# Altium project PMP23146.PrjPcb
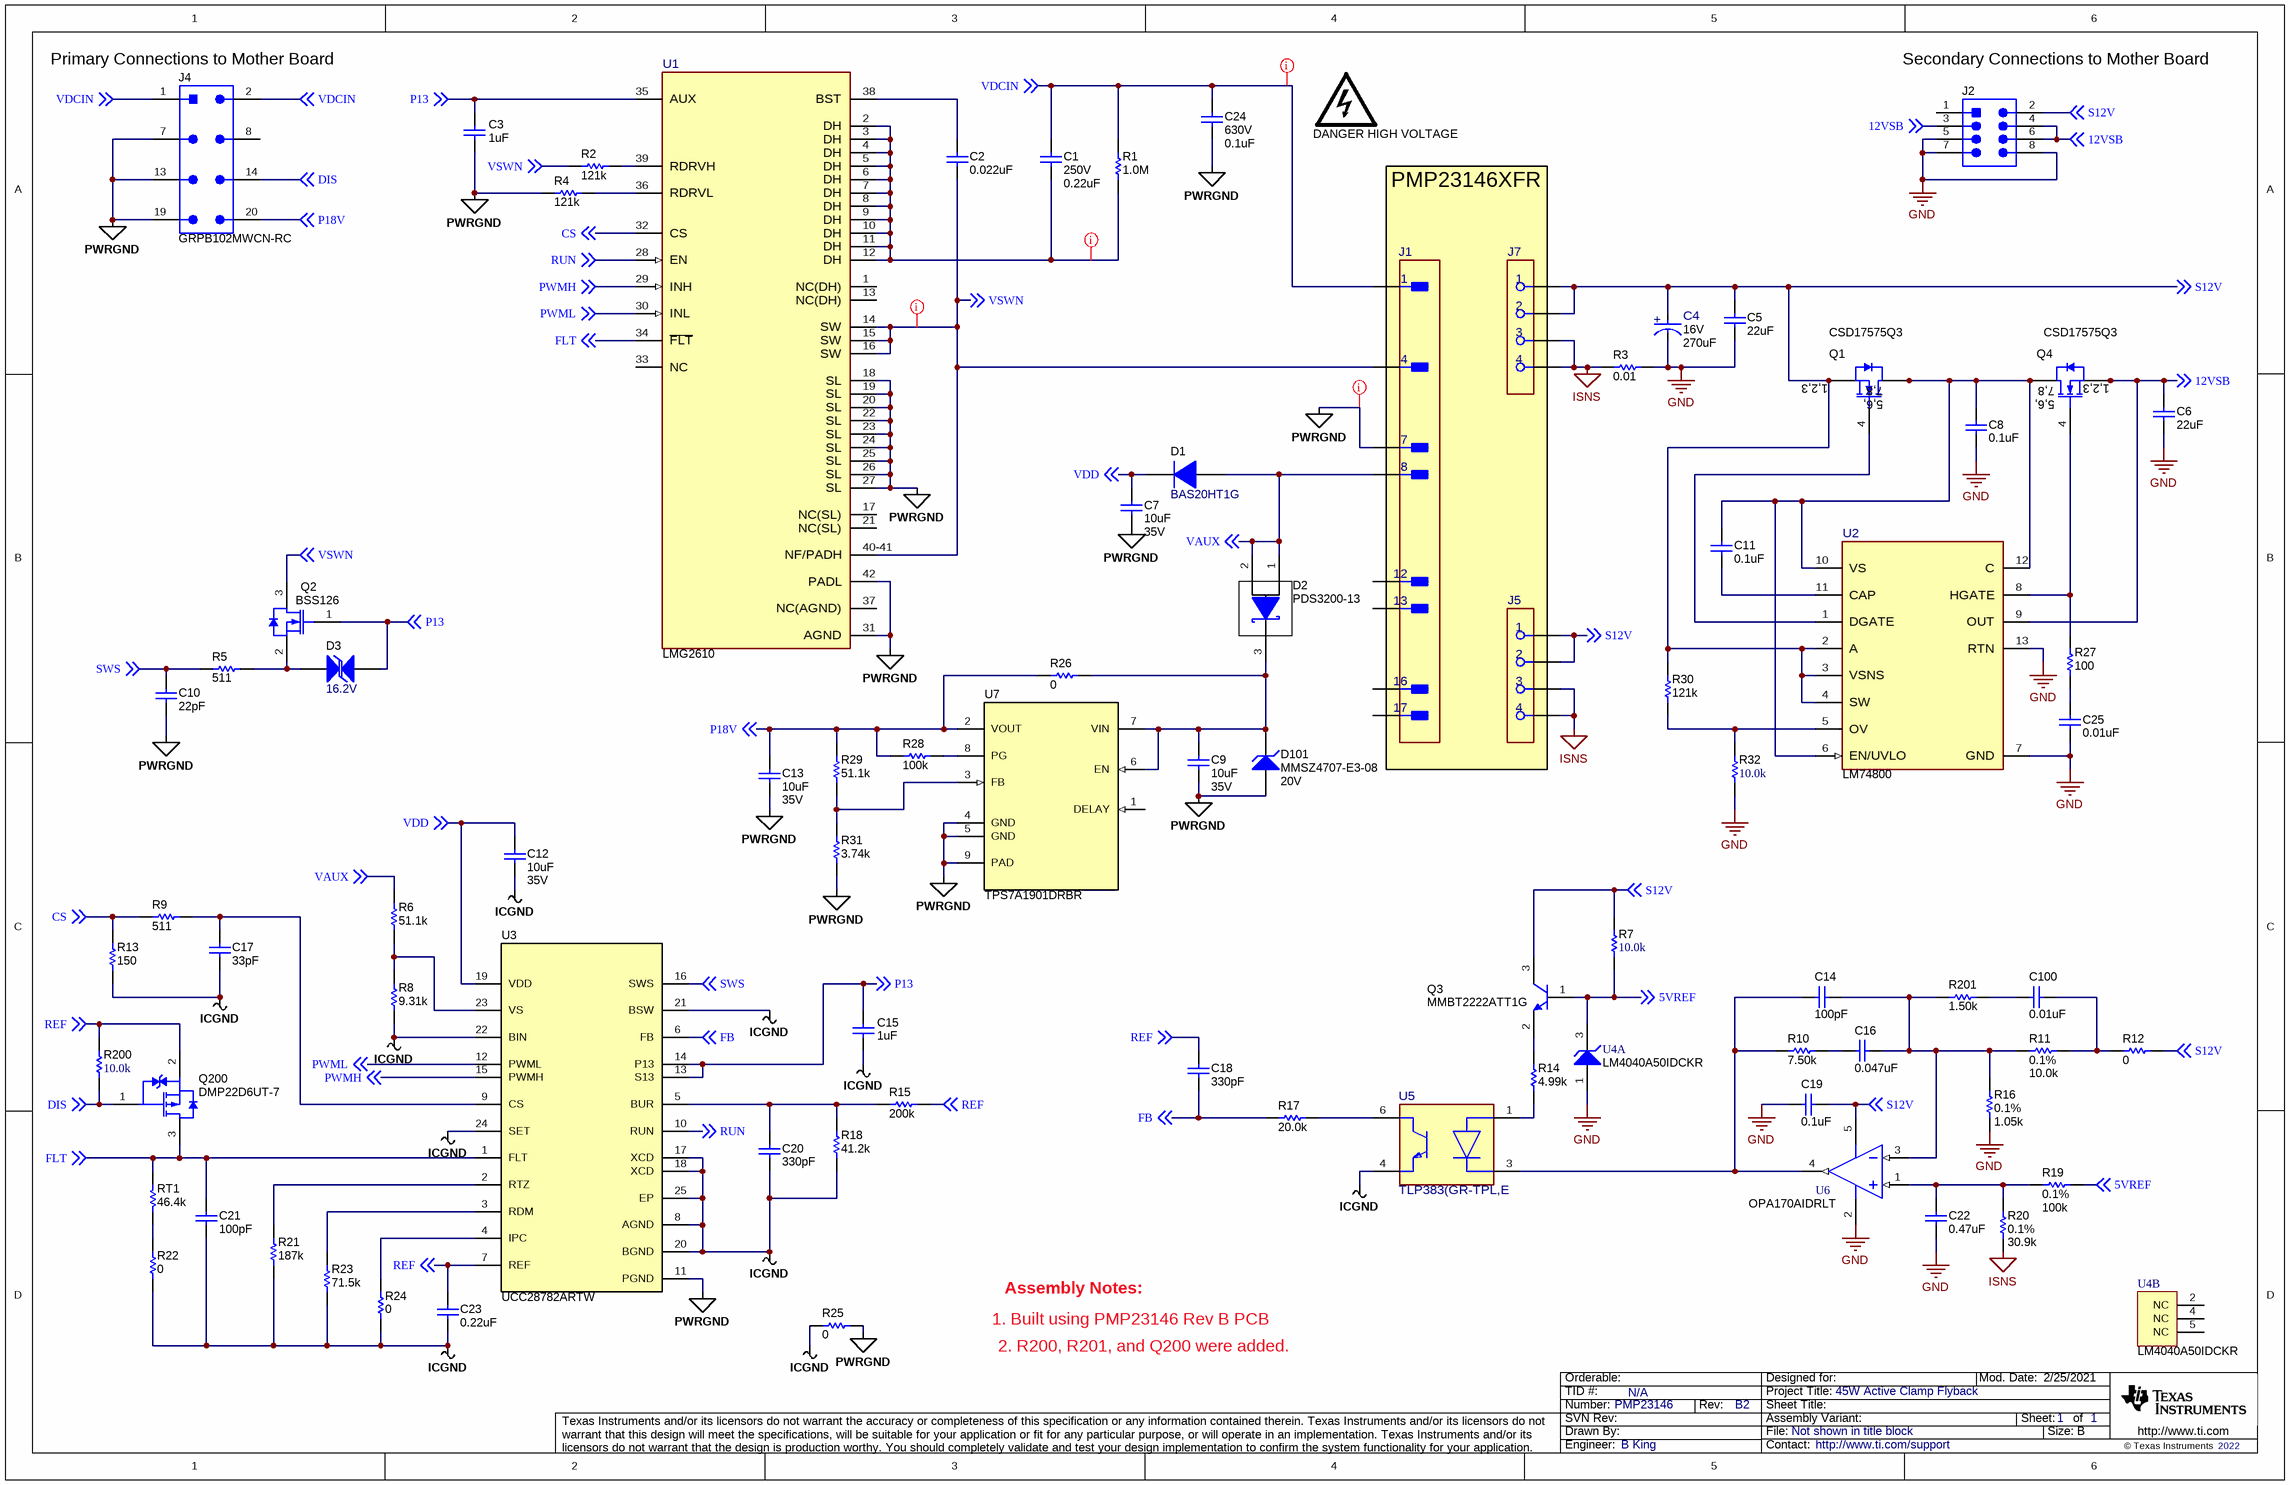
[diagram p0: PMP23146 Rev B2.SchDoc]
CopyrightYear: 2022; PCB_Layout: B King; PCB_Rev: B2; PRJ_Engineer: B King; PRJ_Number: PMP23146; PRJ_Title: 45W Active Clamp Flyback; SCH_Rev: B2; TechSupport: http://www.ti.com/support; TID: N/A
1 sheet, 83 parts. Net scope: global (net labels, ports and power ports of the same name join across sheets).
Board file: PMP23146 Rev B2.PcbDoc

## Sheet PMP23146 Rev B2.SchDoc
size 431 x 279 mm; Date: Not shown in title block; ApprovedBy: Not shown in title block; CheckedBy: Not shown in title block; Author: Not shown in title block; CompanyName: Not shown in title block; Engineer: Not shown in title block; Organization: Not shown in title block; Address1: Not shown in title block; Address2: Not shown in title block; Address3: Not shown in title block; Address4: Not shown in title block; DocumentNumber: 1; Revision: Use project parameter SCH_Rev; SheetNumber: 1; SheetTotal: 1; PageSetup: Record=PageOptions¦CenterHorizontal=True¦CenterVertical=True¦PrintScale=1.00¦XCorrection=1.00¦YCorrection=1.00¦PrintKind=0¦BorderSize=5000000¦LeftOffset=0¦BottomOffset=0¦Orientation=2¦PaperLength=1000¦PaperWidth=1000¦Scale=100¦PaperSource=15¦PrintQuality=600¦MediaType=1¦DitherType=10¦PaperKind=Letter¦PrintScaleMode=1

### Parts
C1  VDC_V: 250V  ValueDisplayed: 0.22uF  [1206_190L]  (hidden comment: C3216X7T2E224K160AA)
C2  ValueDisplayed: 0.022uF  [0402S]  (hidden comment: GRM155R71H223KA12D)
C3  ValueDisplayed: 1uF  [0603S]  (hidden comment: C1608X7R1E105K080AB)
C4  VDC_V: 16V  ValueDisplayed: 270uF  [FP-APSG160ELL271MF08J_RADIAL-MFG]  (hidden comment: APSG160ELL271MF08J)
C5  ValueDisplayed: 22uF  [1206_180L]  (hidden comment: C3216X5R1V226M160AC)
C6  ValueDisplayed: 22uF  [1206_180L]  (hidden comment: C3216X5R1V226M160AC)
C7  ValueDisplayed: 10uF  VDC_V: 35V  [0603S]  (hidden comment: GRM188R6YA106MA73D)
C8  ValueDisplayed: 0.1uF  [0402S]  (hidden comment: GRM155R71E104KE14D)
C9  ValueDisplayed: 10uF  VDC_V: 35V  [0603S]  (hidden comment: GRM188R6YA106MA73D)
C10  ValueDisplayed: 22pF  [0402S]  (hidden comment: GRM1555C1H220JA01D)
C11  ValueDisplayed: 0.1uF  [0402S]  (hidden comment: GRM155R71E104KE14D)
C12  ValueDisplayed: 10uF  VDC_V: 35V  [0603S]  (hidden comment: GRM188R6YA106MA73D)
C13  ValueDisplayed: 10uF  VDC_V: 35V  [0603S]  (hidden comment: GRM188R6YA106MA73D)
C14  ValueDisplayed: 100pF  [0402S]  (hidden comment: GRM1555C1H101JA01D)
C15  ValueDisplayed: 1uF  [0603S]  (hidden comment: C1608X7R1E105K080AB)
C16  ValueDisplayed: 0.047uF  [0402S]  (hidden comment: GRM155R71E473KA88D)
C17  ValueDisplayed: 33pF  [0402S]  (hidden comment: GRM1555C1H330JA01D)
C18  ValueDisplayed: 330pF  [0402S]  (hidden comment: GRM155R71H331KA01D)
C19  ValueDisplayed: 0.1uF  [0402S]  (hidden comment: GRM155R71E104KE14D)
C20  ValueDisplayed: 330pF  [0402S]  (hidden comment: GRM155R71H331KA01D)
C21  ValueDisplayed: 100pF  [0402S]  (hidden comment: GRM1555C1H101JA01D)
C22  ValueDisplayed: 0.47uF  [0402S]  (hidden comment: C1005X5R1A474K050BB)
C23  ValueDisplayed: 0.22uF  [0402S]  (hidden comment: GRM155R71C224KA12D)
C24  VDC_V: 630V  ValueDisplayed: 0.1uF  [1808_215_L]  (hidden comment: C1808W104KBRACTU)
C25  ValueDisplayed: 0.01uF  [0402S]  (hidden comment: GCM155R71E103KA37D)
C100  ValueDisplayed: 0.01uF  [0402S]  (hidden comment: GCM155R71E103KA37D)
D1  BAS20HT1G  [SOD-323]
D2  PDS3200-13  [POWERDI5]
D3  value 16.2V  [SOD-323-Bi]  (hidden comment: DF2B18FU)
D101  MMSZ4707-E3-08  value 20V  [SOD-123]
J1  LPPB171NFFN-RC  [FP-GRPB171VWVN-RC_HDR17-MFG]  (value not drawn)
J2  GRPB042MWCN-RC  [Sullins_GRPB042MWCN]  (value not drawn)
J4  GRPB102MWCN-RC  [Sullins_GRPB102MWCN-modified]
J5  LPPB041NFFN-RC  [FP-LPPB041NFFN-RC_HDR04-MFG]  (value not drawn)
J7  LPPB041NFFN-RC  [FP-LPPB041NFFN-RC_HDR04-MFG]  (value not drawn)
LOGO1  DANGER HIGH VOLTAGE  [IEC_HighVoltage_Small]  (no BOM)
Q1  CSD17575Q3  [DQG0008A_NV]
Q2  BSS126  [SOT-23L]
Q3  MMBT2222ATT1G  [SOT-416]
Q4  CSD17575Q3  [DQG0008A_NV]
Q200  DMP22D6UT-7  [SOT-523]
R1  ValueDisplayed: 1.0M  [1206L]  (hidden comment: CRCW12061M00JNEA)
R2  ValueDisplayed: 121k  [0402S]  (hidden comment: CRCW0402121KFKED)
R3  ValueDisplayed: 0.01  [1206L]  (hidden comment: CSR1206FK10L0)
R4  ValueDisplayed: 121k  [0402S]  (hidden comment: CRCW0402121KFKED)
R5  ValueDisplayed: 511  [0402S]  (hidden comment: CRCW0402511RFKED)
R6  ValueDisplayed: 51.1k  [0402S]  (hidden comment: CRCW040251K1FKED)
R7  ValueDisplayed: 10.0k  [0402S]  (hidden comment: CRCW040210K0FKED)
R8  ValueDisplayed: 9.31k  [0402S]  (hidden comment: CRCW04029K31FKED)
R9  ValueDisplayed: 511  [0402S]  (hidden comment: CRCW0402511RFKED)
R10  ValueDisplayed: 7.50k  [0402S]  (hidden comment: CRCW04027K50FKED)
R11  Tolerance_%: 0.1%  ValueDisplayed: 10.0k  [0402S]  (hidden comment: MCR01MRTF1002)
R12  ValueDisplayed: 0  [0402S]  (hidden comment: CRCW04020000Z0ED)
R13  ValueDisplayed: 150  [0402S]  (hidden comment: CRCW0402150RFKED)
R14  ValueDisplayed: 4.99k  [0402S]  (hidden comment: CRCW04024K99FKED)
R15  ValueDisplayed: 200k  [0402S]  (hidden comment: CRCW0402200KFKED)
R16  Value1: 0.1%  ValueDisplayed: 1.05k  [0402S]  (hidden comment: ERA-2AEB1051X)
R17  ValueDisplayed: 20.0k  [0402S]  (hidden comment: CRCW040220K0FKED)
R18  ValueDisplayed: 41.2k  [0402S]  (hidden comment: CRCW040241K2FKED)
R19  Value1: 0.1%  ValueDisplayed: 100k  [0402S]  (hidden comment: RG1005P-104-B-T5)
R20  Value1: 0.1%  ValueDisplayed: 30.9k  [0402S]  (hidden comment: ERA-2AEB3092X)
R21  ValueDisplayed: 187k  [0402S]  (hidden comment: CRCW0402187KFKED)
R22  ValueDisplayed: 0  [0402S]  (hidden comment: CRCW04020000Z0ED)
R23  ValueDisplayed: 71.5k  [0402S]  (hidden comment: CRCW040271K5FKED)
R24  ValueDisplayed: 0  [0402S]  (hidden comment: CRCW04020000Z0ED)
R25  ValueDisplayed: 0  [0402S]  (hidden comment: CRCW04020000Z0ED)
R26  ValueDisplayed: 0  [0402S]  (hidden comment: CRCW04020000Z0ED)
R27  ValueDisplayed: 100  [0402S]  (hidden comment: CRCW0402100RFKED)
R28  ValueDisplayed: 100k  [0402S]  (hidden comment: CRCW0402100KFKED)
R29  ValueDisplayed: 51.1k  [0402S]  (hidden comment: CRCW040251K1FKED)
R30  ValueDisplayed: 121k  [0402S]  (hidden comment: CRCW0402121KFKED)
R31  ValueDisplayed: 3.74k  [0402S]  (hidden comment: CRCW04023K74FKED)
R32  ValueDisplayed: 10.0k  [0402S]  (hidden comment: CRCW040210K0FKED)
R200  ValueDisplayed: 10.0k  [0402S]  (hidden comment: CRCW040210K0FKED)
R201  ValueDisplayed: 1.50k  [0402S]  (hidden comment: CRCW04021K50FKED)
RT1  ValueDisplayed: 46.4k  [0603L]  (hidden comment: CRCW060346K4FKEA)
U1  LMG2610  [RRG0040A-C01-MFG]
U2  LM74800  [DRR0012E-MFG]
U3  UCC28782ARTW  [RTW0024B]
U4  LM4040A50IDCKR  [DCK0005A_N]  (parts A,B of 2)
U5  TLP383(GR-TPL,E  [FP-TLP383(GR-TPL,E_SO6-4-MFG]
U6  OPA170AIDRLT  [DRL0005A]
U7  TPS7A1901DRBR  [DRB0008B]

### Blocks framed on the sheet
PMP23146XFR: J1 J5 J7

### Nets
GND: C4.1(CATHODE) C5.1 C6.2 C8.2 C19.1 C22.1 C25.1 J2.5 J2.7 J2.8 R3.2 R16.1 R32.1 U2.7(GND) U2.13(RTN) U4.1(ANODE) U6.2(V-)
ICGND: C12.2 C15.1 C17.2 C20.1 C21.2 C23.2 R8.1 R13.1 R18.1 R21.1 R22.1 R23.1 R24.1 R25.2 U3.8(AGND) U3.17(XCD) U3.18(XCD) U3.20(BGND) U3.21(BSW) U3.22(BIN) U3.24(SET) U3.25(EP) U5.4(Emitter)
ISNS: J5.3 J5.4 J7.3 J7.4 R3.1 R20.1
PWRGND: C3.1 C7.2 C9.2 C10.1 C13.2 C24.2 D101.2(A) J1.7 J4.7 J4.13 J4.19 R4.2 R25.1 R31.1 U1.18(SL) U1.19(SL) U1.20(SL) U1.22(SL) U1.23(SL) U1.24(SL) U1.25(SL) U1.26(SL) U1.27(SL) U1.31(AGND) U1.42(PADL) U3.11(PGND) U7.4(GND) U7.5(GND) U7.9(PAD)
5VREF: Q3.1(B) R7.1 R19.1 U4.3(CATHODE) ; off-sheet 5VREF
12VSB: C6.1 J2.3 J2.4 J2.6 Q4.1(S) Q4.2(S) Q4.3(S) U2.9(OUT) ; off-sheet 12VSB
CS: R9.1 R13.2 U1.32(CS) ; off-sheet CS
DIS: J4.14 Q200.1(G) R200.1 ; off-sheet DIS
FB: C18.1 R17.1 U3.6(FB) ; off-sheet FB
FLT: C21.1 Q200.3(D) RT1.1 U1.34(~{FLT}) U3.1(FLT) ; off-sheet FLT
P13: C3.2 C15.2 D3.2 Q2.1(G) U1.35(AUX) U3.13(S13) U3.14(P13) ; off-sheet P13
P18V: C13.1 J4.20 R26.2 R28.2 R29.2 U7.2(VOUT) ; off-sheet P18V
PWMH: U1.29(INH) U3.15(PWMH) ; off-sheet PWMH
PWML: U1.30(INL) U3.12(PWML) ; off-sheet PWML
REF: C18.2 C23.1 Q200.2(S) R15.2 R200.2 U3.7(REF) ; off-sheet REF
RUN: U1.28(EN) U3.10(RUN) ; off-sheet RUN
S12V: C4.2(ANODE) C5.2 C19.2 J2.2 J5.1 J5.2 J7.1 J7.2 Q1.1(S) Q1.2(S) Q1.3(S) Q3.3(C) R7.2 R12.1 R30.2 U2.2(A) U2.3(VSNS) U2.4(SW) U6.5(V+) ; off-sheet S12V
SWS: C10.2 R5.1 U3.16(SWS) ; off-sheet SWS
VAUX: D1.2(A) D2.1(A) D2.2(A) J1.8 R6.2 ; off-sheet VAUX
VDCIN: C1.1 C24.1 J1.1 J4.1 J4.2 R1.2 ; off-sheet VDCIN
VDD: C7.1 C12.1 D1.1(K) U3.19(VDD) ; off-sheet VDD
VSWN: C2.2 J1.4 Q2.3(D) R2.1 U1.14(SW) U1.15(SW) U1.16(SW) U1.40-41(NF/PADH) ; off-sheet VSWN
NetC1_2: C1.2 R1.1 U1.2(DH) U1.3(DH) U1.4(DH) U1.5(DH) U1.6(DH) U1.7(DH) U1.8(DH) U1.9(DH) U1.10(DH) U1.11(DH) U1.12(DH)
NetC2_1: C2.1 U1.38(BST)
NetC8_1: C8.1 C11.1 Q1.5(D) Q1.6(D) Q1.7(D) Q1.8(D) Q1.9(D) Q4.5(D) Q4.6(D) Q4.7(D) Q4.8(D) Q4.9(D) U2.6(EN/UVLO) U2.10(VS) U2.12(C)
NetC9_1: C9.1 D2.3(K) D101.1(K) R26.1 U7.6(EN) U7.7(VIN)
NetC11_2: C11.2 U2.11(CAP)
NetC14_1: C14.1 R10.1 U5.3(Cathode) U6.4(OUT)
NetC14_2: C14.2 C16.1 R11.1 R16.2 R201.1 U6.3(IN-)
NetC16_2: C16.2 R10.2
NetC17_1: C17.1 R9.2 U3.9(CS)
NetC20_2: C20.2 R15.1 R18.2 U3.5(BUR)
NetC22_2: C22.2 R19.2 R20.2 U6.1(IN+)
NetC25_2: C25.2 R27.1
NetC100_1: C100.1 R201.2
NetC100_2: C100.2 R11.2 R12.2
NetD3_1: D3.1 Q2.2(S) R5.2
NetQ1_4: Q1.4(G) U2.1(DGATE)
NetQ3_2: Q3.2(E) R14.2
NetQ4_4: Q4.4(G) R27.2 U2.8(HGATE)
NetR2_2: R2.2 U1.39(RDRVH)
NetR4_1: R4.1 U1.36(RDRVL)
NetR6_1: R6.1 R8.2 U3.23(VS)
NetR14_1: R14.1 U5.1(Anode)
NetR17_2: R17.2 U5.6(Collector)
NetR21_2: R21.2 U3.2(RTZ)
NetR22_2: R22.2 RT1.2
NetR23_2: R23.2 U3.3(RDM)
NetR24_2: R24.2 U3.4(IPC)
NetR28_1: R28.1 U7.8(PG)
NetR29_1: R29.1 R31.2 U7.3(FB)
NetR30_1: R30.1 R32.2 U2.5(OV)

Not connected (* = marked no-connect by the designer): J1 12 13 16 17; J2 1; J4 8; U1 1(NC(DH)) 13(NC(DH)) 17(NC(SL)) 21(NC(SL)) 33(NC) 37(NC(AGND)); U4 2(NC) 4(NC) 5(NC); U7 1(DELAY)

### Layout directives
net class 400V: NetC1_2, VDCIN, VSWN
net class Primary LV: PWRGND

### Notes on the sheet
- (near J4) Primary Connections to Mother Board
- (near J2) Secondary Connections to Mother Board
- Assembly Notes:
- 2. R200, R201, and Q200 were added.
- 1. Built using PMP23146 Rev B PCB

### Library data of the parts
C1 = CMP-0008726-2: CAP, CERM, 0.22 uF, 250 V, +/- 10%, X7T, 1206_190; Manufacturer: TDK; TaMin_C: -55°C; Polarized: N; SizeAreaWB_mm2: 10.92; Value1: Unknown; U/M: EA; Value: 0.22uF; TaMax_C: 125°C; SizeZ_mm: 1.9; SizeX_mm: 3.2; SizeY_mm: 1.6; Cap_Case: 1206; SizeArea_mm2: 5.12; Cap_F: 220nF; AEC Category: Q200
C2 = CMP-0006684-2: CAP, CERM, 0.022 uF, 50 V, +/- 10%, X7R, 0402; Manufacturer: MuRata; TaMin_C: -55°C; Polarized: N; SizeAreaWB_mm2: 3; Value1: Unknown; U/M: EA; TaMax_C: 125°C; SizeZ_mm: 0.6; SizeX_mm: 1; SizeY_mm: 0.5; Cap_Case: 0402; Value2: 50V; Cap_F: 22nF; AEC Category: Q200
C3 C15 = CMP-0007040-4: CAP, CERM, 1 µF, 25 V, +/- 10%, X7R, 0603; Manufacturer: TDK; Polarized: N; CompType: Capacitor; Value: 1uF; U/M: EA; Cap_F: 1µF; Value1: Unknown; VDC_V: 25V; TaMin_C: -55°C; TaMax_C: 125°C; Cap_Case: 0603; AEC Category: Q200; SizeArea_mm2: 1.28; SizeAreaWB_mm2: 4.68; SizeX_mm: 1.6; SizeY_mm: 0.8; SizeZ_mm: 1
C4 = CMP-0091874-1: 270µF 16V Aluminum - Polymer Capacitors Radial, Can 10mOhm 20000 Hrs @ 105°C; Manufacturer: Nippon Chemi-Con; IRMS_A: 5.08A; AEC Qualified: No; Esr: 0.01; Tolerance_%: 20%; SizeZ_mm: 9.2mm; Dissipation Factor: 12%; Life: 20000Hours; Leakage Current: 864uA
C5 C6 = CMP-0008667-2: CAP, CERM, 22 uF, 35 V, +/- 20%, X5R, 1206; Manufacturer: TDK; TaMin_C: -55°C; ESR_ohm: 2.398m; Polarized: N; SizeAreaWB_mm2: 10.92; Value1: 0.002398 ohm; U/M: EA; Value: 22uF; TaMax_C: 85°C; SizeZ_mm: 1.8; SizeX_mm: 3.2; SizeY_mm: 1.6; Cap_Case: 1206_180; Value2: 35V; SizeArea_mm2: 5.12; Cap_F: 22µF; IRMS_A: 4.68507A; AEC Category: Q200
C7 C9 C12 C13 = CMP-0007355-6: CAP, CERM, 10 uF, 35 V, +/- 20%, X5R, 0603; Manufacturer: Murata; TaMax_C: 85°C; Value1: Unknown; TaMin_C: -55°C; Value: 10uF; SizeZ_mm: 1; SizeArea_mm2: 1.28; AEC Category: Q200; Cap_F: 10µF; SizeY_mm: 0.8; AEC Qualified: N; SizeX_mm: 1.6; SizeAreaWB_mm2: 4.68; U/M: EA; Cap_Case: 0603
C8 C11 C19 = CMP-0006659-2: CAP, CERM, 0.1 uF, 25 V, +/- 10%, X7R, 0402; Manufacturer: MuRata; TaMin_C: -55°C; Polarized: N; SizeAreaWB_mm2: 3; Value1: Unknown; U/M: EA; Value: 0.1uF; TaMax_C: 125°C; SizeZ_mm: 0.6; SizeX_mm: 1; SizeY_mm: 0.5; Cap_Case: 0402; Value2: 25V; Cap_F: 100nF; AEC Category: Q200
C10 = CMP-0006439-2: CAP, CERM, 22 pF, 50 V, +/- 5%, C0G/NP0, 0402; Manufacturer: MuRata; TaMin_C: -55°C; Polarized: N; SizeAreaWB_mm2: 3; Value1: Unknown; U/M: EA; Value: 22pF; TaMax_C: 125°C; SizeZ_mm: 0.6; SizeX_mm: 1; SizeY_mm: 0.5; Cap_Case: 0402; Value2: 50V; AEC Category: Q200
C14 C21 = CMP-0006410-2: CAP, CERM, 100 pF, 50 V, +/- 5%, C0G/NP0, 0402; Manufacturer: MuRata; TaMin_C: -55°C; Polarized: N; SizeAreaWB_mm2: 3; Value1: Unknown; U/M: EA; Value: 100pF; TaMax_C: 125°C; SizeZ_mm: 0.6; SizeX_mm: 1; SizeY_mm: 0.5; Cap_Case: 0402; Value2: 50V; AEC Category: Q200
C16 = CMP-0006669-2: CAP, CERM, 0.047 uF, 25 V, +/- 10%, X7R, 0402; Manufacturer: MuRata; TaMin_C: -55°C; Polarized: N; SizeAreaWB_mm2: 3; Value1: Unknown; U/M: EA; TaMax_C: 125°C; SizeZ_mm: 0.6; SizeX_mm: 1; SizeY_mm: 0.5; Cap_Case: 0402; Value2: 25V; Cap_F: 47nF; AEC Category: Q200
C17 = CMP-0006454-2: CAP, CERM, 33 pF, 50 V, +/- 5%, C0G/NP0, 0402; Manufacturer: MuRata; TaMin_C: -55°C; Polarized: N; SizeAreaWB_mm2: 3; Value1: Unknown; U/M: EA; Value: 33pF; TaMax_C: 125°C; SizeZ_mm: 0.6; SizeX_mm: 1; SizeY_mm: 0.5; Cap_Case: 0402; Value2: 50V; AEC Category: Q200
C18 C20 = CMP-0006687-2: CAP, CERM, 330 pF, 50 V, +/- 10%, X7R, 0402; Manufacturer: MuRata; TaMin_C: -55°C; Polarized: N; SizeAreaWB_mm2: 3; Value1: Unknown; U/M: EA; Value: 330pF; TaMax_C: 125°C; SizeZ_mm: 0.6; SizeX_mm: 1; SizeY_mm: 0.5; Cap_Case: 0402; Value2: 50V; AEC Category: Q200
C22 = CMP-0006267-3: CAP, CERM, 0.47 uF, 10 V, +/- 10%, X5R, 0402; Manufacturer: TDK; AEC Category: Q200; SizeZ_mm: 0.6; SizeY_mm: 0.5; SizeX_mm: 1; Value2: 10V; MFG_Status: TI_Obsolete; SizeAreaWB_mm2: 3; Cap_Case: 0402; Cap_F: 470nF; TaMin_C: -55°C; TaMax_C: 85°C; U/M: EA; Value: 0.47uF; Value1: Unknown; Polarized: N
C23 = CMP-0006648-2: CAP, CERM, 0.22 µF, 16 V, +/- 10%, X7R, 0402; Manufacturer: MuRata; TaMin_C: -55°C; Polarized: N; SizeAreaWB_mm2: 3; Value1: Unknown; U/M: EA; Value: 0.22uF; TaMax_C: 125°C; SizeZ_mm: 0.6; SizeX_mm: 1; SizeY_mm: 0.5; Cap_Case: 0402; Value2: 16V; Cap_F: 220nF; AEC Category: Q200
C24 = CMP-0009318-2: CAP, CERM, 0.1 uF, 630 V, +/- 10%, X7R, 1808; Manufacturer: Kemet; TaMin_C: -55°C; Polarized: N; SizeAreaWB_mm2: 16.5; Value1: Unknown; U/M: EA; Value: 0.1uF; TaMax_C: 125°C; SizeZ_mm: 2.15; SizeX_mm: 4.5; SizeY_mm: 2; Cap_Case: 1808; SizeArea_mm2: 9; Cap_F: 100nF; AEC Category: Q200
C25 C100 = CMP-0006352-2: CAP, CERM, 0.01 uF, 25 V, +/- 10%, X7R, 0402; Manufacturer: MuRata; TaMin_C: -55°C; Polarized: N; SizeAreaWB_mm2: 3; Value1: Unknown; U/M: EA; Value: 0.01uF; TaMax_C: 125°C; SizeZ_mm: 0.6; SizeX_mm: 1; SizeY_mm: 0.5; Cap_Case: 0402; Value2: 25V; Cap_F: 10nF; AEC Category: Q200
D1 = CMP-0029150-2: Diode, Switching, 200 V, 0.2 A, AEC-Q101, SOD-323; Manufacturer: ON Semiconductor; Value2: 1.25V; Value1: 0.2A; SizeZ_mm: 1; Green_REACh: Incomplete; SizeArea_mm2: 3.645; Vr_V: 200V; SizeX_mm: 2.7; TJmax_C: 150°C; Io_A: 200mA; Value: 200V; Green_Lifecycle: Not Set; SizeAreaWB_mm2: 8.695; AEC Qualified: Y; AEC Category: Q101; SizeY_mm: 1.35
D2 = CMP-0077025-2: Diode, Schottky, 200 V, 3 A, PowerDI5; Manufacturer: Diodes Inc.; Green_REACh: Incomplete; Value2: 0.78V; TJmax_C: 150°C; Green_Lifecycle: Not Set; Io_A: 3A; SizeX_mm: 6.4; SizeAreaWB_mm2: 49.56; Vf_V: 780mV; SizeY_mm: 3.9; AEC Category: Q101; SizeArea_mm2: 24.96; Value: 200V; SizeZ_mm: 1.05
D3 = CMP-0005821-3: Diode, TVS, Bi, 16.2 V, SOD-323; Manufacturer: Toshiba; PartNumber: DF2B18FU,H3F; SizeAreaWB_mm2: 8.695; Ppk: 80W; SizeZ_mm: 1; SizeY_mm: 1.35; SizeArea_mm2: 3.645; VRWM: 15V; SizeX_mm: 2.7
D101 = CMP-0077617-3: Diode, Zener, 20 V, 500 mW, SOD-123; Manufacturer: Vishay-Semiconductor; Power_W: 500mW; AEC Category: Q101; SizeX_mm: 3.85; AEC Qualified: N; SizeZ_mm: 1.35; RJA_CperW: 340; Value1: 0.5W; SizeAreaWB_mm2: 13.095; SizeArea_mm2: 6.545; SizeY_mm: 1.7
J1 = CMP-BK1: Connector Socket Through Hole 17 position 0.050" (1.27mm); Manufacturer: Sullins Connector Solutions; Part Number: GRPB171VWVN-RC; Conn Gender: Male; SizeZ_mm: 4.4mm; ContactFinish: Gold; Current_A: 1A; Row_Count: 1; Conn Orientation: Straight; AEC Qualified: No
J2 = CMP-0086278-1: Header, 1.27mm, 4x2, Gold, R/A, TH; Manufacturer: Sullins Connector Solutions; Current_A: 1A; Shrouded: N; Pitch_mm: 1.27; Voltage_V: 500V; Gender: Male; Row_Count: 2
J4 = CMP-0054702-2: Header, 50mil, 10x2, Gold, R/A, TH; Manufacturer: Sullins Connector Solutions
J5 J7 = CMP-0092135-1: Manufacturer: Sullins Connector Solutions; Row_Count: 1; AEC Qualified: No; Conn Gender: Female; Current_A: 1A; Is Female: yes; ContactFinish: Gold,Nickel; SizeZ_mm: 4.7mm; DUT-Pitch_mm: 1.27mm; Conn Orientation: Straight
LOGO1 = CMP-0074835-1: IEC 61010-1 High Voltage Warning; SymbolCreator: a0412235
Q1 Q4 = CMP-0000587-1: MOSFET, N-CH, 30 V, 60 A, DQG0008A (VSON-CLIP-8); Alternate Manufacturer: None; Manufacturer: Texas Instruments; SizeZ_mm: 1.1; ChType: N; Value2: 23 nC; Value1: 0.003; VdsMax_V: 30V; SizeX_mm: 3.3; Vgs_V: 20V; Value: 30V; Rdson45_ohm: 3.2m; SizeArea_mm2: 10.89; AEC Category: Q101; IdsMax_A: 60A; SizeAreaWB_mm2: 18.49; U/M: EA; QgTyp_nC: 23
Q2 = CMP-0067574-1: MOSFET, N-CH, 600 V, 0.021 A, AEC-Q101, SOT-23; PartNumber: BSS126H6327XTSA2; Manufacturer: Infineon Technologies; Alternate Manufacturer: None; U/M: EA; ChType: N; Value: 600V; Value1: ? ohm; Value2: 1.4 nC; QgTyp_nC: 1.4; Vgs_V: 20V; IdsMax_A: 21mA; SizeAreaWB_mm2: 14.0; SizeArea_mm2: 7.5; SizeX_mm: 2.5; SizeY_mm: 3.0; SizeZ_mm: 1.1; AEC Category: Q101; AEC Qualified: Y
Q3 = CMP-0078773-2: Transistor, NPN, 40 V, 0.6 A, AEC-Q101, SOT-416; Manufacturer: ON Semiconductor; Value: 40 V; Value1: 0.6 A; NPN: 1; PNP: 0; Vceo_V: 40V; AEC Category: Q101; SizeZ_mm: 0.95; AEC Qualified: Y; TaMin_C: -55°C; SizeArea_mm2: 2.56; Vcesat1_V: 300mV; IcRated_A: 600mA; TaMax_C: 150°C; CompType: BJT; SizeX_mm: 1.6; SizeAreaWB_mm2: 6.76
Q200 = CMP-0000039-3: MOSFET, P-CH, -20 V, -0.43 A, AEC-Q101, SOT-523; Alternate Manufacturer: None; Manufacturer: Diodes Inc.; SizeY_mm: 1.6; SizeAreaWB_mm2: 6.76; AEC Qualified: Y; VdsMax_V: -20V; Rdson45_ohm: 1.1; Value: -20V; SizeArea_mm2: 2.56; Vgs_V: -8V; Value1: 1; AEC Category: Q101; IdsMax_A: -430mA; SizeZ_mm: 0.8; ChType: P; ChMode: Enhancement
R1 = CMP-0018610-3: RES, 1.0 M, 5%, 0.25 W, AEC-Q200 Grade 0, 1206; Manufacturer: Vishay-Dale; Power_W: 250mW; TempCo: 200 ppm/C; Value_Code: 1M00; Value: 1.0Meg; EIA_Code: E24; Res_ohm: 1M; SizeX_mm: 3.2; SizeY_mm: 1.6; SizeZ_mm: 1.35; Value2: 0.25W; SizeArea_mm2: 5.12; AEC Qualified: Y; VDC_V: 200V; AEC Category: Q200; AEC Grade: 0
R2 R4 R30 = CMP-0025984-3: RES, 121 k, 1%, 0.063 W, AEC-Q200 Grade 0, 0402; Manufacturer: Vishay-Dale; Power_W: 63mW; TempCo: 100 ppm/C; Value: 121k; EIA_Code: E96; SizeX_mm: 1; SizeY_mm: 0.5; SizeZ_mm: 0.6; Value2: 0.063W; AEC Qualified: Y; VDC_V: 50V; AEC Category: Q200; AEC Grade: 0
R3 = CMP-0017256-2: RES, 0.01, 1%, 0.5 W, 1206; Manufacturer: Stackpole Electronics Inc; Power_W: 500mW; TempCo: 100 ppm/C; Value_Code: R010; U/M: EA; Value: 0.01; EIA_Code: E96; Res_ohm: 10m; SizeX_mm: 3.2; SizeY_mm: 1.6; SizeZ_mm: 1.35; Value2: 0.5W; SizeArea_mm2: 5.12; AEC Category: Q200
R5 R9 = CMP-0026436-2: RES, 511, 1%, 0.063 W, AEC-Q200 Grade 0, 0402; Manufacturer: Vishay-Dale; Power_W: 63mW; TempCo: 100 ppm/C; Value_Code: 511R; Value: 511; EIA_Code: E96; SizeX_mm: 1; SizeY_mm: 0.5; SizeZ_mm: 0.6; Value2: 0.063W; AEC Qualified: Y; VDC_V: 50V; AEC Category: Q200; AEC Grade: 0
R6 R29 = CMP-0026437-2: RES, 51.1 k, 1%, 0.063 W, AEC-Q200 Grade 0, 0402; Manufacturer: Vishay-Dale; Power_W: 63mW; TempCo: 100 ppm/C; Value_Code: 51k1; Value: 51.1k; EIA_Code: E96; SizeX_mm: 1; SizeY_mm: 0.5; SizeZ_mm: 0.6; Value2: 0.063W; AEC Qualified: Y; VDC_V: 50V; AEC Category: Q200; AEC Grade: 0
R7 R32 R200 = CMP-0025958-1: RES, 10.0 k, 1%, 0.063 W, 0402; Manufacturer: Vishay-Dale; Power_W: 63mW; TempCo: 100 ppm/C; Value_Code: 10k0; U/M: EA; Value: 10.0k; EIA_Code: E96; Res_ohm: 10k; SizeX_mm: 1; SizeY_mm: 0.5; SizeZ_mm: 0.6; Value2: 0.063W; VDC_V: 50V; AEC Category: Q200
R8 = CMP-0026620-3: RES, 9.31 k, 1%, 0.063 W, AEC-Q200 Grade 0, 0402; Manufacturer: Vishay-Dale; Power_W: 63mW; TempCo: 100 ppm/C; Value_Code: 9k31; Value: 9.31k; EIA_Code: E96; SizeX_mm: 1; SizeY_mm: 0.5; SizeZ_mm: 0.6; Value2: 0.063W; AEC Qualified: Y; VDC_V: 50V; AEC Category: Q200; AEC Grade: 0
R10 = CMP-0026555-2: RES, 7.50 k, 1%, 0.063 W, AEC-Q200 Grade 0, 0402; Manufacturer: Vishay-Dale; Power_W: 63mW; TempCo: 100 ppm/C; Value_Code: 7k50; Value: 7.50k; EIA_Code: E96; Res_ohm: 7.5k; SizeX_mm: 1; SizeY_mm: 0.5; SizeZ_mm: 0.6; Value2: 0.063W; AEC Qualified: Y; VDC_V: 50V; AEC Category: Q200; AEC Grade: 0
R11 = CMP-0026793-1: RES, 10.0 k, 0.1%, 0.063 W, 0402; Manufacturer: Rohm; Power_W: 63mW; TempCo: 100 ppm/C; Value_Code: 10k0; U/M: EA; Value: 10.0k; EIA_Code: E192; Res_ohm: 10k; SizeX_mm: 1; SizeY_mm: 0.5; SizeZ_mm: 0.6; Value2: 0.063W; AEC Qualified: N; VDC_V: 50V; AEC Category: Q200
R12 R22 R24-R26 = CMP-0026822-3: RES, 0, 5%, 0.063 W, AEC-Q200 Grade 0, 0402; Manufacturer: Vishay-Dale; Power_W: 63mW; TempCo: 200 ppm/C; Value_Code: 0000; Value: 0; EIA_Code: E24; SizeX_mm: 1; SizeY_mm: 0.5; SizeZ_mm: 0.6; Value2: 0.063W; CompType: Resistor; AEC Qualified: Y; VDC_V: 50V; AEC Category: Q200
R13 = CMP-0026022-3: RES, 150, 1%, 0.063 W, AEC-Q200 Grade 0, 0402; Manufacturer: Vishay-Dale; Power_W: 63mW; TempCo: 100 ppm/C; Value_Code: 150R; Value: 150; EIA_Code: E96; SizeX_mm: 1; SizeY_mm: 0.5; SizeZ_mm: 0.6; Value2: 0.063W; AEC Qualified: Y; VDC_V: 50V; AEC Category: Q200; AEC Grade: 0
R14 = CMP-0026414-2: RES, 4.99 k, 1%, 0.063 W, AEC-Q200 Grade 0, 0402; Manufacturer: Vishay-Dale; Power_W: 63mW; TempCo: 100 ppm/C; Value_Code: 4k99; Value: 4.99k; EIA_Code: E96; SizeX_mm: 1; SizeY_mm: 0.5; SizeZ_mm: 0.6; Value2: 0.063W; AEC Qualified: Y; VDC_V: 50V; AEC Category: Q200; AEC Grade: 0
R15 = CMP-0026158-2: RES, 200 k, 1%, 0.063 W, AEC-Q200 Grade 0, 0402; Manufacturer: Vishay-Dale; Power_W: 63mW; TempCo: 100 ppm/C; Value: 200k; EIA_Code: E96; SizeX_mm: 1; SizeY_mm: 0.5; SizeZ_mm: 0.6; Value2: 0.063W; AEC Qualified: Y; VDC_V: 50V; AEC Category: Q200; AEC Grade: 0
R16 = CMP-0026776-1: RES, 1.05 k, 0.1%, 0.063 W, 0402; Manufacturer: Panasonic; Power_W: 63mW; TempCo: 25 ppm/C; Value_Code: 33k0; U/M: EA; Value: 1.05k; SizeX_mm: 1; SizeY_mm: 0.5; SizeZ_mm: 0.6; Value2: 0.063W; VDC_V: 50V; AEC Category: Q200
R17 = CMP-0026162-2: RES, 20.0 k, 1%, 0.063 W, AEC-Q200 Grade 0, 0402; Manufacturer: Vishay-Dale; Power_W: 63mW; TempCo: 100 ppm/C; Value_Code: 20k0; Value: 20.0k; EIA_Code: E96; Res_ohm: 20k; SizeX_mm: 1; SizeY_mm: 0.5; SizeZ_mm: 0.6; Value2: 0.063W; AEC Qualified: Y; VDC_V: 50V; AEC Category: Q200; AEC Grade: 0
R18 = CMP-0026371-2: RES, 41.2 k, 1%, 0.063 W, AEC-Q200 Grade 0, 0402; Manufacturer: Vishay-Dale; Power_W: 63mW; TempCo: 100 ppm/C; Value_Code: 41k2; Value: 41.2k; EIA_Code: E96; SizeX_mm: 1; SizeY_mm: 0.5; SizeZ_mm: 0.6; Value2: 0.063W; AEC Qualified: Y; VDC_V: 50V; AEC Category: Q200; AEC Grade: 0
R19 = CMP-0026815-1: RES, 100 k, 0.1%, 0.063 W, 0402; Manufacturer: Susumu Co Ltd; Power_W: 63mW; TempCo: 25 ppm/C; U/M: EA; Value: 100k; EIA_Code: E192; SizeX_mm: 1; SizeY_mm: 0.5; SizeZ_mm: 0.6; Value2: 0.063W; AEC Category: Q200
R20 = CMP-0026776-1: RES, 30.9 k, 0.1%, 0.063 W, 0402; Manufacturer: Panasonic; Power_W: 63mW; TempCo: 25 ppm/C; Value_Code: 33k0; U/M: EA; Value: 30.9k; SizeX_mm: 1; SizeY_mm: 0.5; SizeZ_mm: 0.6; Value2: 0.063W; VDC_V: 50V; AEC Category: Q200
R21 = CMP-0026056-3: RES, 187 k, 1%, 0.063 W, AEC-Q200 Grade 0, 0402; Manufacturer: Vishay-Dale; Power_W: 63mW; TempCo: 100 ppm/C; Value: 187k; EIA_Code: E96; SizeX_mm: 1; SizeY_mm: 0.5; SizeZ_mm: 0.6; Value2: 0.063W; AEC Qualified: Y; VDC_V: 50V; AEC Category: Q200; AEC Grade: 0
R23 = CMP-0026535-2: RES, 71.5 k, 1%, 0.063 W, AEC-Q200 Grade 0, 0402; Manufacturer: Vishay-Dale; Power_W: 63mW; TempCo: 100 ppm/C; Value_Code: 71k5; Value: 71.5k; EIA_Code: E96; SizeX_mm: 1; SizeY_mm: 0.5; SizeZ_mm: 0.6; Value2: 0.063W; AEC Qualified: Y; VDC_V: 50V; AEC Category: Q200; AEC Grade: 0
R27 = CMP-0025951-3: RES, 100, 1%, 0.063 W, AEC-Q200 Grade 0, 0402; Manufacturer: Vishay-Dale; Power_W: 63mW; TempCo: 100 ppm/C; Value_Code: 100R; Value: 100; EIA_Code: E96; SizeX_mm: 1; SizeY_mm: 0.5; SizeZ_mm: 0.6; Value2: 0.063W; AEC Qualified: Y; VDC_V: 50V; AEC Category: Q200; AEC Grade: 0
R28 = CMP-0025950-3: RES, 100 k, 1%, 0.063 W, AEC-Q200 Grade 0, 0402; Manufacturer: Vishay-Dale; Power_W: 63mW; TempCo: 100 ppm/C; Value: 100k; EIA_Code: E96; SizeX_mm: 1; SizeY_mm: 0.5; SizeZ_mm: 0.6; Value2: 0.063W; AEC Qualified: Y; VDC_V: 50V; AEC Category: Q200; AEC Grade: 0
R31 = CMP-0026338-2: RES, 3.74 k, 1%, 0.063 W, AEC-Q200 Grade 0, 0402; Manufacturer: Vishay-Dale; Power_W: 63mW; TempCo: 100 ppm/C; Value_Code: 3k74; Value: 3.74k; EIA_Code: E96; SizeX_mm: 1; SizeY_mm: 0.5; SizeZ_mm: 0.6; Value2: 0.063W; AEC Qualified: Y; VDC_V: 50V; AEC Category: Q200; AEC Grade: 0
R201 = CMP-0026088-3: RES, 1.50 k, 1%, 0.063 W, AEC-Q200 Grade 0, 0402; Manufacturer: Vishay-Dale; Power_W: 63mW; TempCo: 100 ppm/C; Value_Code: 1k50; Value: 1.50k; EIA_Code: E96; Res_ohm: 1.5k; SizeX_mm: 1; SizeY_mm: 0.5; SizeZ_mm: 0.6; Value2: 0.063W; AEC Qualified: Y; VDC_V: 50V; AEC Category: Q200; AEC Grade: 0
RT1 = CMP-0022434-4: RES, 46.4 k, 1%, 0.1 W, AEC-Q200 Grade 0, 0603; Manufacturer: Vishay-Dale; Power_W: 100mW; TempCo: 100 ppm/C; Value_Code: 46k4; Value: 46.4k; EIA_Code: E96; SizeX_mm: 1.6; SizeY_mm: 0.8; SizeZ_mm: 1; Value2: 0.1W; SizeArea_mm2: 1.28; AEC Qualified: Y; VDC_V: 75V; AEC Category: Q200; AEC Grade: 0
U1 = CMP-0093339-2: Integrated 650-V GaN Half-Bridge for Active Clamp Flyback Converters; Part Number: LMG2610_epodB; Manufacturer: Texas Instruments; Propagation Delay: 50ns; Min Supply Voltage: 10V; Standoff Height: 0mm; Number Of Outputs: 1; AEC Qualified: No; Output Voltage: 650V; Turn On Delay Time: 25ns; CompType: IC; AEC Category: Q200; SizeZ_mm: 1mm; TJmax_C: +125°C; Max Supply Voltage: 26V; Nominal Supply Current: 20-1000uA
U2 = CMP-0089212-1: Ideal Diode Controller with Load Dump Protection; Manufacturer: Texas Instruments; Number Of Outputs: 1; TJmax_C: +150°C; Standoff Height: 0mm; AEC Qualified: Yes; Max Supply Voltage: 65V; TaMin_C: -40°C; SizeZ_mm: 0.8mm; TaMax_C: +125°C; Nominal Supply Current: 428uA; AEC Grade: Grade 1; Min Supply Voltage: 3V
U3 = CMP-0086087-1: UCC28782ARTW, RTW0024B (WQFN-24); Manufacturer: Texas Instruments; SizeY_mm: 4; SizeZ_mm: 0.8; AEC Category: Q200; SizeArea_mm2: 16; CompType: IC; AEC Qualified: N; SizeAreaWB_mm2: 25
U4 = CMP-0032800-2: Precision Micropower Shunt Voltage Reference, 0.1% accuracy, 5 V, 15 ppm / degC, 15 mA, -40 to 85 degC, 5-pin SC70 (DCK), Green (RoHS & no Sb/Br); Manufacturer: Texas Instruments; Iout/Iz(Max)(mA): 15; Min Iz for Regulation(uA): 74; Rating: Catalog; Initial Accuracy @ 25/deg C(%): 0.1; VO(V): 5; Temp Coeff(Max)(ppm/ degree C): 100; AEC Category: Q200; AEC Qualified: N; CompType: IC; SizeAreaWB_mm2: 9.3; SizeArea_mm2: 4.2; SizeX_mm: 2.1; SizeY_mm: 2.0; SizeZ_mm: 1.1
U5 = CMP-0087394-2: Optoisolator Transistor Output 5000Vrms 1 Channel 6-SO; Manufacturer: Toshiba; CTR (Max): 300%; CTR (Min): 100%; SizeZ_mm: 2.3mm
U6 = CMP-0040524-2: MicroPower, Rail-to-Rail Output, General Purpose Operational Amplifier, 2.7 to 36 V, -40 to 125 degC, 5-pin SOT23 (DRL5), Green (RoHS & no Sb/Br); Manufacturer: Texas Instruments; Sub Family: High Supply Voltage Amplifier (>=30V), Low Power Amp (<=500uA), Low Supply Voltage Amplifier (<=2.7V), Precision Amplifier; Total Supply Voltage(Min)(+5V is 5, +/-5V is 10): 2.7; Slew Rate(Typ)(V/us): 0.4; GBW(Typ)(MHz): 1.2; Total Supply Voltage(Max)(+5V is 5, +/-5V is 10): 36; IIB(Max)(pA): 15; Vio (25C)(Max)(mV): 1.8; Rating: Catalog; Offset Drift(Typ)(uV/C): 0.3; Iq per channel(Max)(mA): 0.145; Packing: SMALL T&R; CMRR(Min)(dB): 104; Number of Channels: 1
U7 = CMP-0073863-3: 40-V, 450-mA, Low IQ, Low-Dropout Voltage Regulator with Power Good, DRB0008B (VSON-8); Alternate PartNumber: TPS7A1901DRBT; Manufacturer: Texas Instruments; SizeZ_mm: 1.0; SizeX_mm: 3.0; SizeArea_mm2: 9.0; CompType: IC; SizeAreaWB_mm2: 16.0; AEC Category: Q200; AEC Qualified: N

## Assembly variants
001: not fitted D101 R26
